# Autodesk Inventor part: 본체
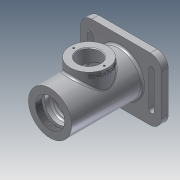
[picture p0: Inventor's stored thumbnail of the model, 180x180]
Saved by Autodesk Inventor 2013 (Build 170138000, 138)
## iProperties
Created: 2021-07
Part Number: 본체
Material: 알루미늄 6061
Document SubType Name: Modeling
Designer: user
Density: 2.71 g/cm^3
Mass: 789.501 g
Surface Area: 658.2 cm^2
Volume: 291.329 cm^3
Author: user
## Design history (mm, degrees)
sketch "스케치1"
  geometry: C1 r 31 at (0, 0); 1 further point
  constraints: 1 centre point, 1 coincident
  dimensions: "d0" = 62 diameter of C1
extrude "돌출1" new body sketch "스케치1" distance "d1" = 115; taper "d2" = 0 deg
node "작업 평면1"
sketch "스케치2"
  geometry: L1 (-58, 45)-(58, 45); L2 (58, 45)-(58, -45); L3 (58, -45)-(-58, -45); L4 (-58, -45)-(-58, 45); L5 (-58, 45)-(58, -45); L6 (58, 45)-(-58, -45); 1 further point
  constraints: 12 end point, 2 midpoint, 2 parallel, 1 horizontal, 1 perpendicular
  dimensions: "d4" = 116 distance of L2.end L3.end; "d5" = 90 distance of L1.end L2.end
extrude "돌출2" join sketch "스케치2" distance "d6" = 10; taper "d7" = 0 deg
sketch "스케치3"
  geometry: C1 r 31 at (0, 0) reference; C2 r 35 at (0, 0)
  constraints: 1 centre point, 1 coincident
  dimensions: "d8" = 70 diameter of C2
extrude "돌출3" join sketch "스케치3" distance "d9" = 3; taper "d10" = 0 deg
node "작업 평면2"
sketch "스케치5"
  geometry: L1 (31, 115)-(-31, 115) reference; L2 (35, 0)-(-35, 0) reference; L3 (0, 115)-(0, 0); L4 (21, 115)-(21, 106); L5 (21, 106)-(24, 106); L6 (24, 106)-(24, 103); L7 (24, 103)-(20, 103); L8 (20, 103)-(20, 94); L9 (20, 94)-(17.5, 94); L10 (17.5, 94)-(17.5, 90.75); L11 (17.5, 90.75)-(18.5, 90.75); L12 (18.5, 90.75)-(18.5, 89); L13 (18.5, 89)-(17.5, 89); L14 (17.5, 89)-(17.5, 78); L15 (17.5, 78)-(26, 78); L16 (26, 78)-(26, 40); L17 (26, 40)-(17.5, 40); L18 (17.5, 40)-(17.5, 29); L19 (17.5, 29)-(16, 29); L20 (16, 29)-(16, 24); L21 (16, 24)-(10, 24); L22 (10, 24)-(10, 21.3); L23 (10, 21.3)-(12.5, 21.3); L24 (12.5, 21.3)-(12.5, 14); L25 (12.5, 14)-(16, 14); L26 (16, 14)-(22, 0)
  constraints: 48 end point, 12 perpendicular, 11 parallel, 2 point on line, 1 midpoint
  dimensions: "d12" = 42 diameter of L4 L3; "d14" = 40 diameter of L8 L3; "d15" = 48 diameter of L6 L3; "d16" = 37 diameter of L12 L3; "d17" = 35 diameter of L14 L3; "d18" = 52 diameter of L16 L3; "d19" = 35 diameter of L18 L3; "d20" = 1.75 distance of L11.end L12.end; "d21" = 32 diameter of L20 L3; "d22" = 20 diameter of L22 L3; "d23" = 25 diameter of L24 L3; "d24" = 44 diameter of L26.end L3; "d25" = 12 distance between parallel lines of L7 L1; "d27" = 21 distance between parallel lines of L9 L1; "d28" = 35 diameter of L10 L3; "d29" = 14 distance from line of L25 L26.end; "d35" = 24 distance between parallel lines of L21 L2; "d36" = 7.3 distance of L23.end L24.end; "d50" = 65 distance between parallel lines of L19 L9; "d51" = 11 distance of L17.end L18.end; "d52" = 3 distance of L5.end L6.end; "d53" = 38 distance of L15.end L16.end; "d55" = 32 diameter of L25.end L3; "d56" = 11 distance of L13.end L14.end
revolve "회전1" sketch "스케치5" stored, may be unused: angle "d38" = 90 deg
feature "스레드1" dims "d39" = 10, "d40" = 0
node "작업 평면3"
sketch "스케치6"
  geometry: L1 (31, 115)-(-31, 115) reference; C1 r 27 at (0, 59); 2 further points
  constraints: 1 centre point, 1 midpoint, 1 vertical alignment
  dimensions: "d42" = 54 diameter of C1; "d43" = 56 distance from line of C1.centre L1
extrude "돌출4" join sketch "스케치6" stored distance "d44" = 3; taper "d45" = 0 deg
sketch "스케치7"
  geometry: C1 r 27 at (0, 0) reference; C2 r 16 at (0, 0); 1 further point
  constraints: 1 centre point, 1 coincident
  dimensions: "d46" = 32 diameter of C2
extrude "돌출5" cut sketch "스케치7" stored distance "d47" = 3; taper "d48" = 0 deg
fillet "모깎기1" dims "d49" = 3
fillet "모깎기2" dims "d57" = 0.3
fillet "모깎기3" dims "d58" = 3
chamfer "모따기1" distance "d59" = 0.7; stored, may be unused: second distance "d60" = 2, angle "d61" = 30 deg
chamfer "모따기2" distance "d62" = 1; stored, may be unused: second distance "d63" = 2, angle "d64" = 30 deg
chamfer "모따기3" distance "d65" = 1; stored, may be unused: second distance "d66" = 2, angle "d67" = 30 deg
sketch "스케치8"
  geometry: C1 r 27 at (0, 0) reference; 2 further points
  constraints: 1 horizontal alignment
  dimensions: "d68" = 22 distance of point (-22, 0) C1.centre
hole "구멍1" sketch "스케치8" at (-22, 0) diameter "d69" = 2.459; stored, may be unused: countersink angle "d73" = 90 deg, drill point angle "d75" = 118 deg; dims "d70" = 6, "d71" = 4, "d72" = 2, "d74" = 8
fillet "모깎기4" dims "d79" = 16
sketch "스케치9" dims "d80" = 8, "d83" = 8
  geometry: L1 (40, 25)-(48, 25); L2 (48, 25)-(48, -25); L3 (48, -25)-(40, -25); L4 (40, -25)-(40, 25); C1 r 31 at (0, 0) reference; 3 further points
  constraints: 8 end point, 2 horizontal alignment, 2 parallel, 1 coincident, 1 horizontal, 1 midpoint, 1 perpendicular, 4 other
  dimensions: "d81" = 44 horizontal distance of point (44, 25) C1.centre; "d82" = 25 vertical distance of point (44, 25) C1.centre; "d84" = 44 horizontal distance of point (44, -25) C1.centre; "d85" = 25 vertical distance of point (44, -25) C1.centre
extrude "돌출6" cut sketch "스케치9" stored distance "d86" = 3; taper "d87" = 0 deg
node "작업 평면4"
sketch "스케치10"
  geometry: L1 (42, 86)-(42, 32) reference; L2 (31, 115)-(-31, 115) reference; 3 further points
  constraints: 1 horizontal alignment, 1 midpoint, 1 other
  dimensions: "d89" = 8 distance from line of point (34, 59) L1; "d91" = 56 distance from line of point (34, 59) L2 (derived)
feature "엠보싱1" sketch "스케치10" dims "d92" = 0.5, "d93" = 0
fillet "모깎기5" dims "d94" = 3
node "솔리드1"
pattern_circular "원형 패턴1" dims angle "d77" = 360 deg
mirror "대칭1"
other parameters: "d3" = -3, "d11" = 42, "d41" = 42
